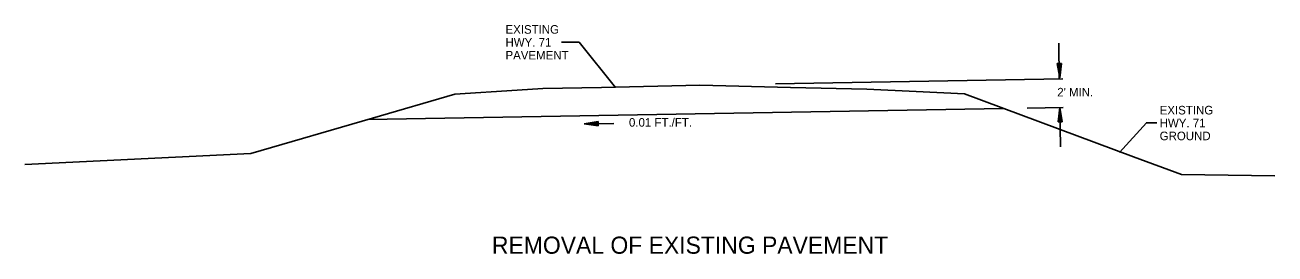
# Model space of a CAD drawing. Extents: x 634177 to 635904, y 289936 to 290970.
# Drawn here: x 635664.7 to 635752.2, y 290540.1 to 290556.1 of the extents above; entities that cross this region are included whole.
import ezdxf

# ---------------------------------------------------------------- set-up
doc = ezdxf.new("R2010")
doc.units = 0
for name, color, linetype in [('Default', 7, 'Continuous'), ('R_Draft', 7, 'Continuous'), ('R_Exist Surface', 7, 'Continuous')]:
    doc.layers.add(name, color=color, linetype=linetype)

msp = doc.modelspace()

# ---------------------------------------------------------------- linework, layer by layer
at = {"layer": 'Default'}
for p, q in [((635737.034, 290554.788), (635737.077, 290552.294)), ((635737.234, 290553.383), (635736.935, 290553.375)), ((635736.935, 290553.375), (635737.111, 290552.381)), ((635736.959, 290553.377), (635737.106, 290552.548)), ((635736.984, 290553.377), (635737.102, 290552.72)), ((635737.01, 290553.378), (635737.097, 290552.887)), ((635737.036, 290553.378), (635737.093, 290553.056)), ((635737.062, 290553.379), (635737.089, 290553.222)), ((635737.109, 290553.382), (635737.089, 290553.222)), ((635737.133, 290553.38), (635737.093, 290553.056)), ((635737.16, 290553.383), (635737.097, 290552.887)), ((635737.186, 290553.383), (635737.102, 290552.72)), ((635737.212, 290553.384), (635737.106, 290552.548)), ((635737.234, 290553.383), (635737.111, 290552.381)), ((635717.213, 290551.947), (635737.317, 290552.298)), ((635688.681, 290549.449), (635733.176, 290550.226)), ((635734.828, 290550.254), (635737.352, 290550.299)), ((635736.987, 290549.292), (635737.111, 290550.294)), ((635737.01, 290549.291), (635737.115, 290550.127)), ((635737.035, 290549.292), (635737.12, 290549.955)), ((635737.061, 290549.292), (635737.124, 290549.788)), ((635737.286, 290549.3), (635737.111, 290550.294)), ((635737.112, 290550.294), (635737.16, 290547.545)), ((635737.263, 290549.298), (635737.115, 290550.127)), ((635737.237, 290549.298), (635737.12, 290549.955)), ((635737.211, 290549.297), (635737.124, 290549.788)), ((635704.807, 290549.31), (635703.812, 290549.143)), ((635705.905, 290549.179), (635703.812, 290549.143)), ((635704.813, 290549.011), (635703.812, 290549.143)), ((635704.809, 290549.286), (635703.979, 290549.146)), ((635704.814, 290549.033), (635703.979, 290549.146)), ((635704.809, 290549.26), (635704.151, 290549.149)), ((635704.813, 290549.059), (635704.151, 290549.149)), ((635704.809, 290549.235), (635704.318, 290549.152)), ((635704.813, 290549.085), (635704.318, 290549.152)), ((635704.81, 290549.209), (635704.487, 290549.154)), ((635704.811, 290549.112), (635704.487, 290549.154)), ((635704.81, 290549.183), (635704.653, 290549.157)), ((635704.813, 290549.136), (635704.653, 290549.157)), ((635704.813, 290549.011), (635704.807, 290549.31)), ((635736.987, 290549.292), (635737.286, 290549.3)), ((635737.088, 290549.295), (635737.128, 290549.619)), ((635737.113, 290549.293), (635737.132, 290549.452)), ((635737.185, 290549.297), (635737.128, 290549.619)), ((635737.16, 290549.296), (635737.132, 290549.452))]:
    msp.add_line(p, q, dxfattribs=at)
for points in [[(635702.239, 290554.861), (635703.463, 290554.861), (635706.018, 290551.703)], [(635743.907, 290549.226), (635743.176, 290549.226), (635741.296, 290547.157)]]:
    msp.add_lwpolyline(points, dxfattribs=at)
at = {"layer": 'R_Exist Surface'}
msp.add_lwpolyline([(635664.691, 290546.318), (635680.485, 290547.07), (635689.007, 290549.544), (635694.784, 290551.227), (635699.135, 290551.509), (635700.935, 290551.619), (635705.041, 290551.703), (635711.929, 290551.855), (635718.271, 290551.699), (635723.596, 290551.587), (635727.067, 290551.426), (635730.431, 290551.25), (635742.258, 290546.837), (635745.636, 290545.609), (635752.17, 290545.523)], dxfattribs=at)

# ---------------------------------------------------------------- texts
at = {"layer": 'Default'}
for s, p in [('EXISTING', (635698.318, 290555.456)), ('HWY. 71', (635698.318, 290554.555)), ('PAVEMENT', (635698.318, 290553.654)), ("2' MIN.", (635736.932, 290551.068)), ('EXISTING', (635744.1, 290549.81)), ('0.01 FT./FT.', (635706.959, 290548.956)), ('HWY. 71', (635744.1, 290548.909)), ('GROUND', (635744.1, 290548.008))]:
    msp.add_text(s, height=0.6, dxfattribs=at).set_placement(p)
at = {"layer": 'R_Draft'}
msp.add_text('REMOVAL OF EXISTING PAVEMENT', height=1.2, dxfattribs=at).set_placement((635697.369, 290540.068))

doc.saveas('drawing.dxf')
